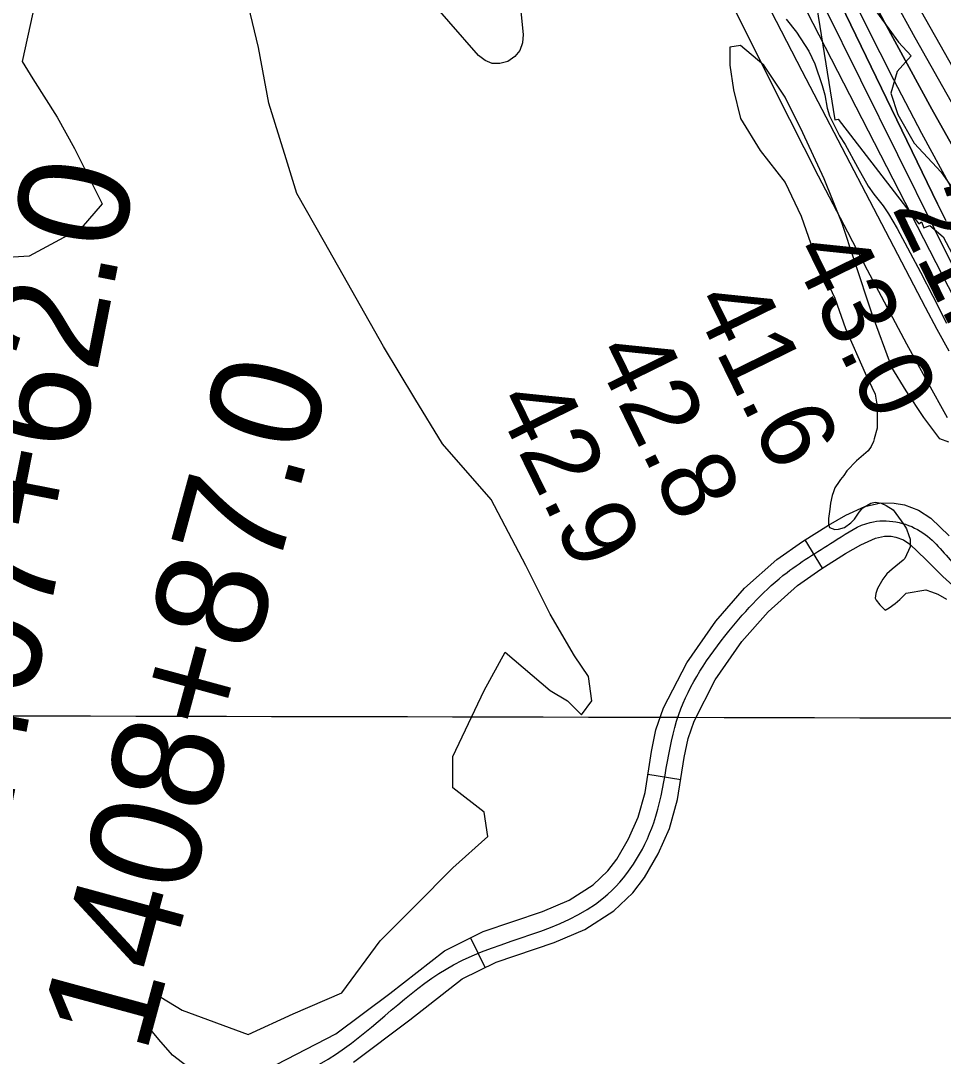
# Model space of a CAD drawing. Extents: x 3187622 to 3225504, y 800805 to 826213.
# Drawn here: x 3197201 to 3198035, y 818051 to 818987 of the extents above; entities that cross this region are included whole.
import ezdxf

# ---------------------------------------------------------------- set-up
doc = ezdxf.new("R2010")
doc.units = 0
for name, color, linetype in [('V-GRID-MAJR', 7, 'Continuous'), ('V-RIVR-EDGE', 7, 'Continuous'), ('V-RIVR-RANG', 7, 'Continuous'), ('V-ROAD-CNTR', 7, 'Continuous'), ('V-RRAP-RVMT', 7, 'Continuous'), ('V-SITE-VEGE', 7, 'Continuous'), ('V-SURV-IDEN', 7, 'Continuous'), ('V-TOPO-DPTH', 7, 'Continuous'), ('V-TOPO-MAJR', 7, 'Continuous'), ('V-TOPO-MINR', 7, 'Continuous'), ('V-TOPO-WATR', 7, 'Continuous')]:
    doc.layers.add(name, color=color, linetype=linetype)

msp = doc.modelspace()

# ---------------------------------------------------------------- linework, layer by layer
at = {"layer": 'V-GRID-MAJR'}
msp.add_spline([(3191823.839, 818371.837), (3197059.682, 818359.272), (3202295.526, 818347.468), (3207531.372, 818336.426), (3212767.22, 818326.145), (3218003.0700000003, 818316.626), (3223238.92, 818307.868), (3223238.921, 818307.868)], degree=3, dxfattribs=at)
at = {"layer": 'V-RIVR-EDGE'}
msp.add_lwpolyline([(3197968.1277814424, 819003.8727811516), (3197994.5538387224, 818967.7290647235), (3198005.825333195, 818955.5301763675), (3197993.1842445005, 818941.2170210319), (3197987.4850822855, 818921.6705500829), (3197993.9579376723, 818902.5286604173), (3198008.672449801, 818876.4115245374), (3198032.949845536, 818850.2707423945), (3198055.040960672, 818818.9192160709)], dxfattribs=at)
at = {"layer": 'V-ROAD-CNTR'}
for p, q in [((3197909.696143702, 818517.8309369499), (3197925.603111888, 818492.3959878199)), ((3197767.976427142, 818306.1133603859), (3197797.6153678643, 818301.4773696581)), ((3197607.494748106, 818158.088656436), (3197620.794721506, 818131.1987102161))]:
    msp.add_line(p, q, dxfattribs=at)
for points in [[(3197423.5171160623, 818039.089894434), (3197485.789991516, 818071.3138299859), (3197534.564893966, 818107.8797568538), (3197584.195794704, 818146.565679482), (3197619.208724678, 818163.88164485), (3197672.630617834, 818181.993608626), (3197696.879569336, 818192.292588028), (3197718.6365258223, 818206.1605602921), (3197731.775499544, 818218.849534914), (3197739.845483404, 818229.3965138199), (3197750.481462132, 818247.7694770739), (3197759.073444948, 818267.2864380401), (3197765.411432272, 818289.7133931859), (3197771.1834207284, 818326.6143193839), (3197775.2374126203, 818346.3182799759), (3197782.0223990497, 818365.969240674), (3197803.013357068, 818406.7541591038), (3197829.270304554, 818444.5500835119), (3197855.2472526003, 818474.119024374), (3197884.3621943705, 818500.229972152), (3197907.6131478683, 818516.528939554), (3197931.2891005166, 818531.3359099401), (3197946.971069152, 818540.2038922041), (3197964.1470348, 818548.0128765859), (3197978.6550057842, 818551.2598700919), (3197990.71198167, 818551.0938704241), (3198000.0199630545, 818549.4548737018), (3198012.630937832, 818544.8498829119), (3198023.63691582, 818537.529897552), (3198040.20188269, 818521.51592958)], [(3197501.789959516, 818045.815880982), (3197552.784857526, 818084.045804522), (3197600.231762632, 818121.027730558), (3197630.724701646, 818136.109700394), (3197683.324596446, 818153.9416647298), (3197710.901541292, 818165.654641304), (3197737.3064884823, 818182.4846076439), (3197754.233454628, 818198.83157495), (3197764.843433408, 818212.69654722), (3197777.273408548, 818234.1695042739), (3197787.373388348, 818257.1144583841), (3197794.7713735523, 818283.2934060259), (3197800.711361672, 818321.2703300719), (3197804.2293546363, 818338.3662958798), (3197809.678343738, 818354.149264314), (3197828.781305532, 818391.264190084), (3197852.934257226, 818426.0321205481), (3197876.60720988, 818452.9770666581), (3197903.0541569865, 818476.6960192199), (3197924.189114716, 818491.51098959), (3197946.633069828, 818505.547961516), (3197960.589041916, 818513.4399457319), (3197973.733015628, 818519.4169337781), (3197981.76699956, 818521.2139301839), (3197987.887987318, 818521.129930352), (3197992.2139786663, 818520.368931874), (3197998.9869651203, 818517.8939368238), (3198004.748953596, 818514.0619444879), (3198019.1859247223, 818500.1059723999), (3198034.4138942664, 818484.9280027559), (3198076.0108110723, 818447.413077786)]]:
    msp.add_lwpolyline(points, dxfattribs=at)
msp.add_spline([(3197108.0137470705, 817982.20200821), (3197162.33863842, 817991.13199035), (3197229.376504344, 818001.8819688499), (3197259.082444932, 817993.6449853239), (3197361.14324081, 818001.169970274), (3197493.7899755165, 818058.5648554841), (3197592.213778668, 818133.79670502), (3197727.971507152, 818194.3225839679), (3197773.223416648, 818262.200448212), (3197795.8503713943, 818360.0592524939), (3197841.10228089, 818435.2911020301), (3197893.7081756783, 818488.4629956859), (3197938.9610851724, 818518.4419357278), (3197968.940025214, 818533.7149051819), (3198014.192934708, 818525.7959210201), (3198044.737873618, 818495.8159809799), (3198127.323708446, 818420.584131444), (3198203.12155685, 818307.4533577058), (3198233.10149689, 818209.029554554), (3198255.7274516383, 818133.79670502), (3198278.353406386, 818073.2718260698), (3198323.60631588, 818005.3939618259), (3198376.2122106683, 817937.515097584), (3198429.383104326, 817900.18217225), (3198459.363044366, 817854.9292627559), (3198466.7170296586, 817832.303308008), (3198489.3429844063, 817756.5054596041), (3198504.614953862, 817703.899564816), (3198542.513878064, 817628.6677152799), (3198633.018697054, 817530.243912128), (3198783.483396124, 817371.8602288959), (3198859.281244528, 817221.3955298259), (3198934.513094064, 817108.264756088)], degree=3, dxfattribs=at)
at = {"layer": 'V-RRAP-RVMT'}
for p, q in [((3197918.824000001, 819009.476999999), (3197936.8650000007, 818897.6299999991)), ((3197936.865000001, 818897.6299999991), (3197940.030000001, 818898.1299999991)), ((3197940.030000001, 818898.1299999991), (3198012.970000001, 818803.645999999)), ((3198012.970000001, 818803.645999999), (3198015.314000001, 818805.476999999)), ((3198015.314000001, 818805.476999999), (3198017.4990000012, 818799.9429999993)), ((3198017.4990000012, 818799.9429999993), (3198022.680000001, 818801.9259999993)), ((3198022.680000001, 818801.925999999), (3198034.9730000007, 818791.8179999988)), ((3198034.973000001, 818791.817999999), (3198094.120000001, 818679.035999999))]:
    msp.add_line(p, q, dxfattribs=at)
at = {"layer": 'V-SITE-VEGE'}
for p, q in [((3197415.955, 818962.882), (3197403.395, 819016.283)), ((3197211.887, 818994.294), (3197202.47, 818950.3150000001)), ((3197892.971, 818988.5040000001), (3197902.38, 818976.87)), ((3197902.38, 818976.87), (3197913.458, 818959.593)), ((3197425.372, 818912.62), (3197415.955, 818962.882)), ((3197851.803, 818964.782), (3197842.159, 818963.175)), ((3197842.159, 818963.175), (3197842.159, 818947.09)), ((3197872.7, 818947.09), (3197851.803, 818964.782)), ((3197913.458, 818959.593), (3197918.819, 818948.323)), ((3197202.47, 818950.3150000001), (3197211.887, 818934.607)), ((3197918.819, 818948.323), (3197925.475, 818928.576)), ((3197842.159, 818947.09), (3197845.374, 818924.572)), ((3197891.988, 818918.1410000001), (3197872.7, 818947.09)), ((3197211.887, 818934.607), (3197233.864, 818900.0530000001)), ((3197845.374, 818924.572), (3197851.803, 818898.839)), ((3197925.475, 818928.576), (3197927.98, 818920.111)), ((3197441.0700000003, 818862.358), (3197425.372, 818912.62)), ((3197908.063, 818885.969), (3197891.988, 818918.1410000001)), ((3197927.98, 818920.111), (3197930.116, 818908.0040000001)), ((3197930.116, 818908.0040000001), (3197932.203, 818901.1510000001)), ((3197233.864, 818900.0530000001), (3197249.562, 818871.781)), ((3197851.803, 818898.839), (3197869.485, 818869.886)), ((3197932.203, 818901.1510000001), (3197933.438, 818898.736)), ((3197933.438, 818898.736), (3197936.326, 818892.701)), ((3197936.326, 818892.701), (3197941.267, 818883.045)), ((3197927.353, 818844.1509999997), (3197908.063, 818885.969)), ((3197941.267, 818883.045), (3197946.191, 818875.412)), ((3197946.191, 818875.412), (3197957.299, 818854.899)), ((3197249.562, 818871.781), (3197274.676, 818821.519)), ((3197869.485, 818869.886), (3197891.988, 818840.934)), ((3197450.489, 818830.943), (3197441.0700000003, 818862.358)), ((3197957.299, 818854.899), (3197967.164, 818837.61)), ((3197891.988, 818840.934), (3197906.458, 818810.373)), ((3197943.428, 818803.941), (3197927.353, 818844.1509999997)), ((3197967.164, 818837.61), (3197972.086, 818830.376)), ((3197475.605, 818786.965), (3197450.489, 818830.943)), ((3197972.086, 818830.376), (3197980.673, 818819.9500000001)), ((3197274.676, 818821.519), (3197255.841, 818799.529)), ((3197980.673, 818819.9500000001), (3197985.592, 818812.718)), ((3197906.458, 818810.373), (3197919.3170000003, 818773.38)), ((3197985.592, 818812.718), (3197993.397, 818799.451)), ((3197255.841, 818799.529), (3197208.747, 818774.398)), ((3197954.682, 818770.1630000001), (3197943.428, 818803.941)), ((3197993.397, 818799.451), (3198014.387, 818760.034)), ((3197528.9760000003, 818692.728), (3197475.605, 818786.965)), ((3197208.747, 818774.398), (3197161.6550000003, 818771.259)), ((3197919.3170000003, 818773.38), (3197936.997, 818736.385)), ((3197970.755, 818721.91), (3197954.682, 818770.1630000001)), ((3198014.387, 818760.034), (3198025.5100000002, 818738.308)), ((3197936.997, 818736.385), (3197946.643, 818709.042)), ((3198025.5100000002, 818738.308), (3198037.867, 818713.765)), ((3197988.437, 818673.657), (3197970.755, 818721.91)), ((3197946.643, 818709.042), (3197964.316, 818668.603)), ((3197557.233, 818645.606), (3197528.9760000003, 818692.728)), ((3197964.316, 818668.603), (3197973.3880000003, 818649.687)), ((3198001.296, 818652.747), (3197988.437, 818673.657)), ((3197973.3880000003, 818649.687), (3197975.109, 818638.7880000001)), ((3198017.3710000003, 818628.622), (3198001.296, 818652.747)), ((3197582.347, 818604.7660000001), (3197557.233, 818645.606)), ((3197975.109, 818638.7880000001), (3197975.299, 818618.982)), ((3198031.836, 818609.321), (3198017.3710000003, 818628.622)), ((3197975.299, 818618.982), (3197972.559, 818609.2539999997)), ((3197626.301, 818554.506), (3197582.347, 818604.7660000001)), ((3197969.794, 818602.356), (3197967.003, 818598.287)), ((3197971.772, 818606.821), (3197969.794, 818602.356)), ((3197972.559, 818609.2539999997), (3197971.772, 818606.821)), ((3198039.877, 818606.1039999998), (3198031.836, 818609.3209999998)), ((3197967.003, 818598.287), (3197956.576, 818589.2939999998)), ((3197956.576, 818589.2939999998), (3197947.768, 818580.317)), ((3197944.9760000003, 818576.246), (3197942.181, 818572.5819999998)), ((3197947.768, 818580.317), (3197944.9760000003, 818576.246)), ((3197936.999, 818564.853), (3197935.8200000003, 818561.203)), ((3197940.987, 818570.551), (3197936.999, 818564.853)), ((3197942.181, 818572.5819999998), (3197940.987, 818570.551)), ((3197934.6380000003, 818557.957), (3197933.086, 818551.072)), ((3197935.8200000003, 818561.203), (3197934.6380000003, 818557.957)), ((3197657.6950000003, 818494.8200000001), (3197626.301, 818554.506)), ((3197932.328, 818545.809), (3197931.1950000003, 818537.307)), ((3197933.086, 818551.072), (3197932.328, 818545.809)), ((3197959.038, 818542.827), (3197962.233, 818546.9)), ((3197962.233, 818546.9), (3197969.47, 818551.011)), ((3197969.47, 818551.011), (3197973.505, 818551.856)), ((3197973.505, 818551.856), (3197978.7660000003, 818551.099)), ((3197978.7660000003, 818551.099), (3197983.233, 818549.12)), ((3197983.233, 818549.12), (3197989.739, 818545.139)), ((3197931.1950000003, 818537.307), (3197931.24, 818532.458)), ((3197951.444, 818533.457), (3197954.647, 818536.7220000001)), ((3197954.647, 818536.7220000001), (3197959.038, 818542.827)), ((3197989.739, 818545.139), (3197999.162, 818531.886)), ((3197931.24, 818532.458), (3197932.08, 818529.232)), ((3197932.08, 818529.232), (3197936.95, 818527.256)), ((3197936.95, 818527.256), (3197940.18, 818527.6919999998)), ((3197940.18, 818527.692), (3197945.826, 818528.958)), ((3197945.826, 818528.958), (3197951.444, 818533.457)), ((3197999.162, 818531.886), (3198001.624, 818527.868)), ((3198001.624, 818527.868), (3198003.705, 818521.822)), ((3198003.705, 818521.822), (3198004.948, 818518.601)), ((3198004.948, 818518.601), (3198005.011, 818511.7299999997)), ((3198005.011, 818511.7299999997), (3198000.2600000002, 818501.175)), ((3197998.659, 818499.542), (3197988.629, 818491.363)), ((3198000.2600000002, 818501.175), (3197998.659, 818499.542)), ((3197679.6720000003, 818450.841), (3197657.6950000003, 818494.8200000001)), ((3197988.629, 818491.363), (3197983.8170000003, 818487.273)), ((3197980.224, 818482.3879999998), (3197975.455, 818473.854)), ((3197983.8170000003, 818487.273), (3197980.224, 818482.3879999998)), ((3197975.455, 818473.854), (3197973.88, 818469.392)), ((3198001.3680000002, 818469.652), (3198019.126, 818472.652)), ((3198019.126, 818472.652), (3198024.396, 818471.081)), ((3198024.396, 818471.081), (3198030.077, 818468.7120000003)), ((3197973.88, 818469.392), (3197973.5130000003, 818465.3470000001)), ((3197973.5130000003, 818465.3470000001), (3197974.343, 818463.334)), ((3197974.343, 818463.334), (3197977.613, 818459.3199999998)), ((3197991.349, 818460.26), (3197995.7630000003, 818463.9400000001)), ((3197995.7630000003, 818463.9400000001), (3198001.3680000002, 818469.652)), ((3198030.077, 818468.7119999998), (3198037.8000000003, 818464.337)), ((3197977.613, 818459.3199999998), (3197982.5100000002, 818454.517)), ((3197982.5100000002, 818454.517), (3197986.129, 818456.571)), ((3197986.129, 818456.571), (3197991.349, 818460.26)), ((3197701.649, 818413.1449999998), (3197679.6720000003, 818450.841)), ((3197620.022, 818381.7309999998), (3197638.86, 818416.2869999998)), ((3197638.86, 818416.2869999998), (3197679.6720000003, 818381.7309999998)), ((3197714.208, 818394.2979999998), (3197701.649, 818413.1449999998)), ((3197717.345, 818372.3059999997), (3197714.208, 818394.2979999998)), ((3197591.7660000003, 818322.046), (3197620.022, 818381.7309999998)), ((3197679.6720000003, 818381.7309999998), (3197695.37, 818372.3059999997)), ((3197695.37, 818372.3059999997), (3197707.929, 818359.7419999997)), ((3197707.929, 818359.742), (3197717.345, 818372.3059999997)), ((3197591.7660000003, 818293.774), (3197591.7660000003, 818322.046)), ((3197620.022, 818271.784), (3197591.7660000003, 818293.774)), ((3197623.162, 818249.795), (3197620.022, 818271.784)), ((3197591.7660000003, 818221.522), (3197623.162, 818249.795)), ((3197557.233, 818186.968), (3197591.7660000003, 818221.522)), ((3197525.8370000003, 818155.554), (3197557.233, 818186.968)), ((3197491.301, 818108.434), (3197525.8370000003, 818155.554)), ((3197447.349, 818089.586), (3197491.301, 818108.434)), ((3197313.473, 818089.3690000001), (3197327.6890000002, 818104.4670000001)), ((3197327.6890000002, 818104.4670000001), (3197346.8850000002, 818092.728)), ((3197317.029, 818076.9230000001), (3197313.473, 818089.3690000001)), ((3197346.8850000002, 818092.728), (3197406.537, 818070.738)), ((3197406.537, 818070.738), (3197447.349, 818089.586)), ((3197325.911, 818066.259), (3197317.029, 818076.9230000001)), ((3197338.3510000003, 818052.0380000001), (3197325.911, 818066.259)), ((3197361.448, 818034.263), (3197338.3510000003, 818052.0380000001))]:
    msp.add_line(p, q, dxfattribs=at)
at = {"layer": 'V-TOPO-DPTH'}
for points in [[(3197285.440291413, 820823.4266761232), (3197357.1005262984, 820581.1051149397), (3197399.501034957, 820442.4887757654), (3197443.611118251, 820304.4362793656), (3197490.285563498, 820167.2295471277), (3197538.6695833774, 820030.5866576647), (3197637.9684557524, 819758.2449352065), (3197642.100502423, 819747.2975902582), (3197646.395464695, 819736.4166858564), (3197650.934800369, 819725.6354422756), (3197655.6370516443, 819714.9206392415), (3197745.2031582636, 819516.9315051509), (3197796.2522975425, 819408.0034633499), (3197849.2202400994, 819300.0490489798), (3197905.066387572, 819193.5550757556), (3197962.831338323, 819088.0347299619), (3198136.1651529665, 818781.2529607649)], [(3197285.440291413, 820823.4266761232), (3197357.1005262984, 820581.1051149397), (3197399.501034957, 820442.4887757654), (3197443.611118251, 820304.4362793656), (3197490.285563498, 820167.2295471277), (3197538.6695833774, 820030.5866576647), (3197637.9684557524, 819758.2449352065), (3197642.100502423, 819747.2975902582), (3197646.395464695, 819736.4166858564), (3197650.934800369, 819725.6354422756), (3197655.6370516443, 819714.9206392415), (3197745.2031582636, 819516.9315051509), (3197796.2522975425, 819408.0034633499), (3197849.2202400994, 819300.0490489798), (3197905.066387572, 819193.5550757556), (3197962.831338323, 819088.0347299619), (3198136.1651529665, 818781.2529607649)], [(3198087.352261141, 818795.6974675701), (3198024.6921706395, 818907.2253278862), (3197981.7052672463, 818985.8031788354), (3197939.918205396, 819064.9969075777), (3197899.9309058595, 819145.1144530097), (3197861.143447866, 819225.8478762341), (3197645.018157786, 819689.0333527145), (3197635.8169049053, 819709.2029558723), (3197626.8485149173, 819729.4732059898), (3197618.2294192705, 819749.8944265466), (3197609.8431865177, 819770.4162940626), (3197560.4638103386, 819894.2780896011), (3197527.811632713, 819976.9027712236), (3197495.491396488, 820059.6559482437), (3197463.669072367, 820142.6018683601), (3197432.1786896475, 820225.6762838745), (3197318.8107751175, 820527.4840718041), (3197305.8293793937, 820561.8127832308), (3197292.747173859, 820596.1027789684), (3197279.513753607, 820630.3347011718), (3197266.179523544, 820664.5279076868)], [(3197266.179523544, 820664.5279076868), (3197279.513753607, 820630.3347011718), (3197292.747173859, 820596.1027789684), (3197305.8293793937, 820561.8127832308), (3197318.8107751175, 820527.4840718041), (3197432.1786896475, 820225.6762838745), (3197463.669072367, 820142.6018683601), (3197495.491396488, 820059.6559482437), (3197527.811632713, 819976.9027712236), (3197560.4638103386, 819894.2780896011), (3197609.8431865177, 819770.4162940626), (3197618.2294192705, 819749.8944265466), (3197626.8485149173, 819729.4732059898), (3197635.8169049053, 819709.2029558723), (3197645.018157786, 819689.0333527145), (3197861.143447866, 819225.8478762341), (3197899.9309058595, 819145.1144530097), (3197939.918205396, 819064.9969075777), (3197981.7052672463, 818985.8031788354), (3198024.6921706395, 818907.2253278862), (3198087.352261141, 818795.6974675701)], [(3198037.181607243, 818806.5631977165), (3198029.7291659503, 818821.6750638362), (3197624.202556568, 819659.6561140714), (3197610.2171165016, 819689.1079229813), (3197596.5236946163, 819718.6922881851), (3197583.268300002, 819748.4754878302), (3197570.304923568, 819778.3912437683), (3197557.744200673, 819808.4800514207), (3197545.4281004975, 819838.6669381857), (3197533.4789344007, 819869.0009436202), (3197521.774391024, 819899.4330281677), (3197508.8983208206, 819933.5266538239), (3197490.828393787, 819981.03626994), (3197472.610636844, 820028.4887347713), (3197454.1711350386, 820075.8554726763), (3197435.5838033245, 820123.1650592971), (3197372.6721197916, 820282.1978774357), (3197337.7165281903, 820374.1522506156), (3197304.4249675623, 820466.6802305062), (3197273.6294533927, 820560.0686204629), (3197244.4979701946, 820654.0306171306)]]:
    msp.add_lwpolyline(points, dxfattribs=at)
at = {"layer": 'V-TOPO-MAJR'}
msp.add_lwpolyline([(3197169.422397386, 820662.3291373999), (3197339.4274428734, 820193.6932356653), (3197370.3069035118, 820110.1952204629), (3197401.875181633, 820026.9633746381), (3197434.4766859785, 819944.1307828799), (3197467.7670078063, 819861.5643604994), (3197519.874590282, 819734.6109011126), (3197527.7891896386, 819715.7925934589), (3197535.918667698, 819697.069801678), (3197544.37046381, 819678.4902837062), (3197553.0371386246, 819660.0062816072), (3197671.606564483, 819412.7077734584), (3197729.1123582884, 819294.2925885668), (3197787.403690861, 819176.2702842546), (3197846.8733315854, 819058.8373008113), (3197907.1285110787, 818941.7971979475), (3198007.945947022, 818748.3536650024), (3198018.4947884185, 818728.3917585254), (3198029.194369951, 818708.51209546), (3198040.12006169, 818688.7557975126)], dxfattribs=at)
at = {"layer": 'V-TOPO-MINR'}
for points in [[(3197285.440291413, 820823.4266761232), (3197357.1005262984, 820581.1051149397), (3197399.501034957, 820442.4887757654), (3197443.611118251, 820304.4362793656), (3197490.285563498, 820167.2295471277), (3197538.6695833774, 820030.5866576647), (3197637.9684557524, 819758.2449352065), (3197642.100502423, 819747.2975902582), (3197646.395464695, 819736.4166858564), (3197650.934800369, 819725.6354422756), (3197655.6370516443, 819714.9206392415), (3197745.2031582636, 819516.9315051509), (3197796.2522975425, 819408.0034633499), (3197849.2202400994, 819300.0490489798), (3197905.066387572, 819193.5550757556), (3197962.831338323, 819088.0347299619), (3198136.1651529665, 818781.2529607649)], [(3197277.791066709, 820810.7815217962), (3197401.7301550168, 820396.8851918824), (3197436.710976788, 820284.8015245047), (3197473.404666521, 820173.3036008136), (3197512.6676581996, 820062.6842926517), (3197553.6435178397, 819952.6507281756), (3197626.7574466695, 819763.0523326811), (3197632.5956628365, 819748.3138308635), (3197638.6111800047, 819733.6499553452), (3197644.8926486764, 819719.0980192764), (3197651.35141835, 819704.6207095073), (3197787.7614187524, 819406.1900875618), (3197839.850997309, 819296.0022662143), (3197893.8015268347, 819186.7634865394), (3197950.543482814, 819078.9482693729), (3198009.146389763, 818972.0820938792), (3198113.192721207, 818788.003390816)], [(3197172.148922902, 820777.1842443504), (3197284.371540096, 820430.7930389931), (3197325.5572133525, 820308.1991125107), (3197368.491882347, 820186.24222389), (3197414.0500449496, 820065.2408920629), (3197461.357203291, 819944.8765980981), (3197552.512612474, 819720.1093209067), (3197555.612544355, 819712.6319402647), (3197558.788853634, 819705.1878483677), (3197562.079729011, 819697.7936895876), (3197565.446981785, 819690.4328195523), (3197615.3905517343, 819583.4468934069), (3197644.1284698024, 819522.7854183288), (3197673.32167341, 819462.3470471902), (3197703.1978053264, 819402.2433319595), (3197733.529222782, 819342.3627206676), (3198044.8062183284, 818736.3781025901)], [(3197244.4979701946, 820654.0306171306), (3197273.6294533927, 820560.0686204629), (3197304.4249675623, 820466.6802305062), (3197337.7165281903, 820374.1522506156), (3197372.6721197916, 820282.1978774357), (3197435.5838033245, 820123.1650592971), (3197454.1711350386, 820075.8554726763), (3197472.610636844, 820028.4887347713), (3197490.828393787, 819981.03626994), (3197508.8983208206, 819933.5266538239), (3197521.774391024, 819899.4330281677), (3197533.4789344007, 819869.0009436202), (3197545.4281004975, 819838.6669381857), (3197557.744200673, 819808.4800514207), (3197570.304923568, 819778.3912437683), (3197583.268300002, 819748.4754878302), (3197596.5236946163, 819718.6922881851), (3197610.2171165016, 819689.1079229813), (3197624.202556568, 819659.6561140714), (3198029.7291659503, 818821.6750638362), (3198037.181607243, 818806.5631977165)], [(3197252.47689589, 820660.7220914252), (3197272.476519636, 820599.9772543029), (3197294.0755540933, 820539.7825543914), (3197316.7408623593, 820479.9546126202), (3197326.875073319, 820454.2361728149), (3197355.243467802, 820381.760939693), (3197383.391845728, 820309.2009296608), (3197411.2101988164, 820236.5137542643), (3197438.8085353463, 820163.7418019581), (3197476.9290593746, 820062.5316946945), (3197498.5910845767, 820005.796731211), (3197520.5931776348, 819949.1957299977), (3197543.105372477, 819892.7956721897), (3197565.957635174, 819836.5295766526), (3197589.606528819, 819779.0477043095), (3197601.107591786, 819751.7197019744), (3197612.8993446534, 819724.5205109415), (3197625.127132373, 819697.514536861), (3197637.6456099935, 819670.6373740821), (3197941.3629063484, 819032.0302454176), (3197965.335473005, 818982.8171994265), (3197989.915127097, 818933.9164505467), (3198015.40541234, 818885.4841473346), (3198041.5027850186, 818837.3641412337)], [(3197692.4333827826, 819474.0373348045), (3198060.3689737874, 818731.3094961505)], [(3197647.5592526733, 819049.1360129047), (3197655.1955509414, 818974.6686668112), (3197654.475397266, 818967.03451706), (3197652.205646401, 818960.270585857), (3197647.6114997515, 818954.8119824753), (3197641.4677559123, 818950.2235976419), (3197634.131048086, 818948.4607256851), (3197627.169638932, 818948.5000867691), (3197620.771177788, 818951.2427974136), (3197614.748015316, 818955.7877410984), (3197561.1520158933, 819017.5218615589)], [(3197844.870512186, 819000.5593655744), (3197870.2317501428, 818949.2293854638), (3197895.87040381, 818898.0397670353), (3197921.9251810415, 818847.0606911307), (3197948.2573739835, 818796.2219769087), (3197966.202421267, 818761.9188906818), (3197983.918916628, 818728.417654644), (3198001.833685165, 818695.0239289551), (3198020.0458634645, 818661.7914687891), (3198038.45631494, 818628.6665189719)]]:
    msp.add_lwpolyline(points, dxfattribs=at)
at = {"layer": 'V-TOPO-WATR'}
msp.add_lwpolyline([(3197266.179523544, 820664.5279076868), (3197279.513753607, 820630.3347011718), (3197292.747173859, 820596.1027789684), (3197305.8293793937, 820561.8127832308), (3197318.8107751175, 820527.4840718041), (3197432.1786896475, 820225.6762838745), (3197463.669072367, 820142.6018683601), (3197495.491396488, 820059.6559482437), (3197527.811632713, 819976.9027712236), (3197560.4638103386, 819894.2780896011), (3197609.8431865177, 819770.4162940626), (3197618.2294192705, 819749.8944265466), (3197626.8485149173, 819729.4732059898), (3197635.8169049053, 819709.2029558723), (3197645.018157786, 819689.0333527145), (3197861.143447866, 819225.8478762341), (3197899.9309058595, 819145.1144530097), (3197939.918205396, 819064.9969075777), (3197981.7052672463, 818985.8031788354), (3198024.6921706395, 818907.2253278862), (3198087.352261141, 818795.6974675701)], dxfattribs=at)

# ---------------------------------------------------------------- texts
at = {"layer": 'V-RIVR-RANG'}
for s, p in [('21.1', (3197988.043335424, 818817.9948775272)), ('43.0', (3197896.034708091, 818778.5031660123)), ('41.6', (3197806.8120335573, 818733.3267083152)), ('42.8', (3197717.9376031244, 818687.4396573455)), ('42.9', (3197628.1335217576, 818643.4475217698))]:
    msp.add_text(s, height=67.00000000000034, rotation=296.10832571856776, dxfattribs=at).set_placement(p)
at = {"layer": 'V-SURV-IDEN'}
for s, height, rotation, p in [('1407+62.0', 100.0000000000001, 78.90285785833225, (3197183.046044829, 818225.8902037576)), ('1408+87.0', 100.00000000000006, 74.78882247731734, (3197313.934826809, 818051.6272240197)), ('1416+96.9', 100.00000000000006, 57.45166413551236, (3197886.4151466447, 817578.82772843))]:
    msp.add_text(s, height=height, rotation=rotation, dxfattribs=at).set_placement(p)

doc.saveas('drawing.dxf')
